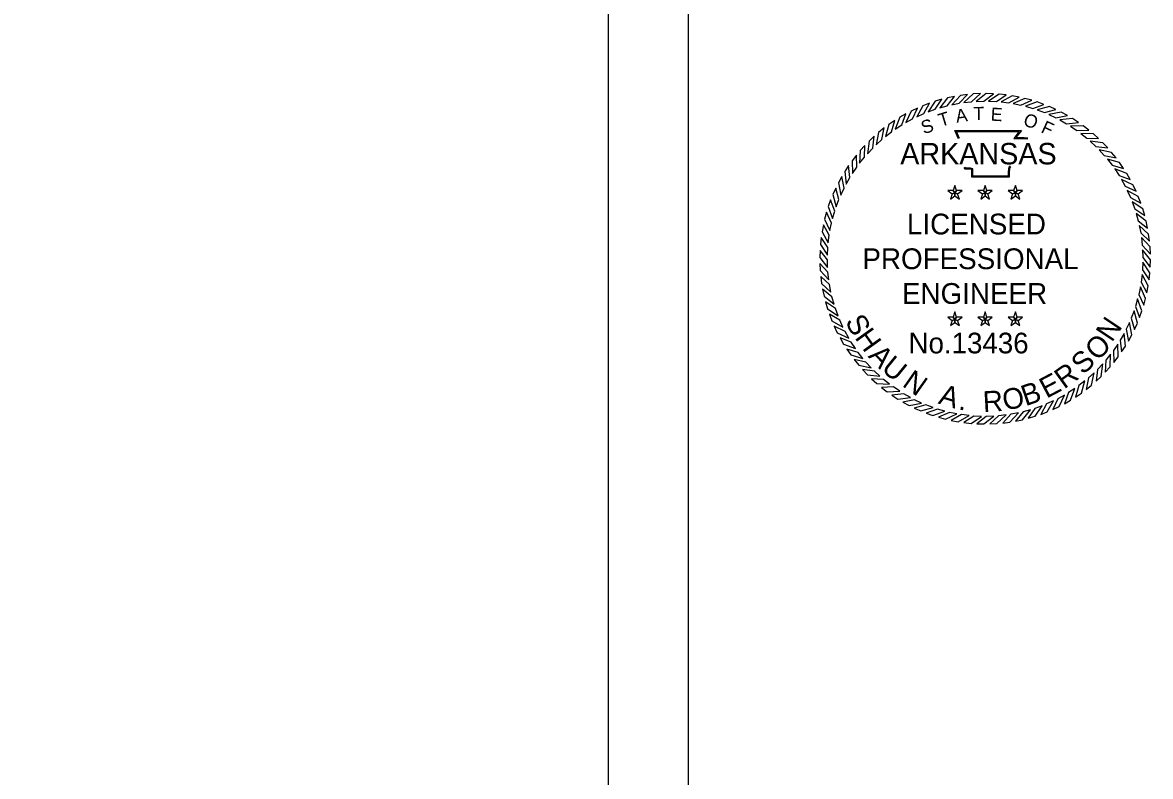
# Model space of a CAD drawing. Extents: x 759422 to 1402138, y 1662254 to 1956530.
# Drawn here: x 1401731 to 1402138, y 1955984.9 to 1956257.2 of the extents above; entities that cross this region are included whole.
import ezdxf

# ---------------------------------------------------------------- set-up
doc = ezdxf.new("R2010")
doc.units = 0
doc.layers.add('1', color=7, linetype='Continuous')
doc.layers.add('G-ANNO-SYMB', color=7, linetype='Continuous')

msp = doc.modelspace()

# ---------------------------------------------------------------- linework, layer by layer
at = {"layer": '1'}
msp.add_line((1401942.43, 1955459.2), (1401942.43, 1956501.52), dxfattribs=at)
msp.add_lwpolyline([(1401971.27, 1956530.36), (1400271.27, 1956530.36), (1400271.27, 1955430.36), (1401971.27, 1955430.36)], close=True, dxfattribs=at)
at = {"layer": 'G-ANNO-SYMB'}
for points in [[(1402058.26, 1956228.04), (1402055.87, 1956227.13), (1402053.61, 1956223.15), (1402056.14, 1956224.29)], [(1402062.73, 1956229.44), (1402060.27, 1956228.72), (1402057.72, 1956224.93), (1402060.32, 1956225.86)], [(1402067.3, 1956230.48), (1402064.79, 1956229.96), (1402061.94, 1956226.38), (1402064.62, 1956227.11)], [(1402071.93, 1956231.17), (1402069.39, 1956230.84), (1402066.27, 1956227.49), (1402068.99, 1956228.01)], [(1402076.61, 1956231.48), (1402074.05, 1956231.36), (1402070.67, 1956228.27), (1402073.43, 1956228.57)], [(1402081.29, 1956231.43), (1402078.73, 1956231.51), (1402075.12, 1956228.69), (1402077.89, 1956228.78)], [(1402085.96, 1956231.02), (1402083.41, 1956231.29), (1402079.59, 1956228.77), (1402082.36, 1956228.64)], [(1402090.58, 1956230.24), (1402088.06, 1956230.71), (1402084.06, 1956228.49), (1402086.81, 1956228.14)], [(1402095.12, 1956229.09), (1402092.64, 1956229.76), (1402088.48, 1956227.87), (1402091.2, 1956227.31)], [(1402099.56, 1956227.6), (1402097.14, 1956228.46), (1402092.85, 1956226.9), (1402095.51, 1956226.12)], [(1402049.72, 1956224.21), (1402047.5, 1956222.93), (1402045.89, 1956218.65), (1402048.21, 1956220.17)], [(1402053.92, 1956226.29), (1402051.6, 1956225.19), (1402049.67, 1956221.05), (1402052.09, 1956222.39)], [(1402103.87, 1956225.76), (1402101.53, 1956226.81), (1402097.12, 1956225.59), (1402099.71, 1956224.61)], [(1402108.02, 1956223.59), (1402105.77, 1956224.82), (1402101.28, 1956223.94), (1402103.79, 1956222.77)], [(1402045.7, 1956221.81), (1402043.58, 1956220.36), (1402042.32, 1956215.96), (1402044.51, 1956217.66)], [(1402111.99, 1956221.1), (1402109.84, 1956222.5), (1402105.29, 1956221.98), (1402107.7, 1956220.61)], [(1402115.75, 1956218.3), (1402113.71, 1956219.87), (1402109.14, 1956219.71), (1402111.44, 1956218.15)], [(1402038.29, 1956216.09), (1402036.42, 1956214.33), (1402035.86, 1956209.79), (1402037.76, 1956211.81)], [(1402041.88, 1956219.09), (1402039.88, 1956217.48), (1402038.97, 1956213), (1402041.02, 1956214.87)], [(1402119.28, 1956215.22), (1402117.37, 1956216.94), (1402112.8, 1956217.14), (1402114.97, 1956215.41)], [(1402034.94, 1956212.81), (1402033.22, 1956210.91), (1402033.02, 1956206.34), (1402034.75, 1956208.51)], [(1402122.55, 1956211.88), (1402120.79, 1956213.74), (1402116.25, 1956214.3), (1402118.27, 1956212.4)], [(1402031.86, 1956209.28), (1402030.29, 1956207.25), (1402030.45, 1956202.68), (1402032.01, 1956204.97)], [(1402125.56, 1956208.28), (1402123.95, 1956210.28), (1402119.47, 1956211.19), (1402121.33, 1956209.14)], [(1402128.27, 1956204.46), (1402126.82, 1956206.58), (1402122.43, 1956207.84), (1402124.13, 1956205.65)], [(1402029.07, 1956205.52), (1402027.66, 1956203.37), (1402028.18, 1956198.83), (1402029.55, 1956201.24)], [(1402130.67, 1956200.44), (1402129.4, 1956202.67), (1402125.11, 1956204.27), (1402126.64, 1956201.95)], [(1402026.58, 1956201.56), (1402025.35, 1956199.3), (1402026.22, 1956194.81), (1402027.4, 1956197.32)], [(1402132.76, 1956196.25), (1402131.66, 1956198.56), (1402127.51, 1956200.5), (1402128.85, 1956198.07)], [(1402024.4, 1956197.4), (1402023.36, 1956195.06), (1402024.58, 1956190.66), (1402025.56, 1956193.25)], [(1402067.4, 1956195.61), (1402066.79, 1956196.45), (1402064.81, 1956196.45), (1402066.41, 1956195.28)], [(1402067.4, 1956195.61), (1402066.41, 1956195.28), (1402065.8, 1956193.4), (1402067.4, 1956194.56)], [(1402067.4, 1956195.61), (1402068.02, 1956196.45), (1402067.4, 1956198.33), (1402066.79, 1956196.45)], [(1402067.4, 1956195.61), (1402068.39, 1956195.28), (1402070, 1956196.45), (1402068.02, 1956196.45)], [(1402067.4, 1956195.61), (1402067.4, 1956194.56), (1402069.01, 1956193.4), (1402068.39, 1956195.28)], [(1402078.31, 1956195.61), (1402077.7, 1956196.45), (1402075.72, 1956196.45), (1402077.32, 1956195.28)], [(1402078.31, 1956195.61), (1402077.32, 1956195.28), (1402076.71, 1956193.4), (1402078.31, 1956194.56)], [(1402078.31, 1956195.61), (1402078.93, 1956196.45), (1402078.31, 1956198.33), (1402077.7, 1956196.45)], [(1402078.31, 1956195.61), (1402079.3, 1956195.28), (1402080.91, 1956196.45), (1402078.93, 1956196.45)], [(1402078.31, 1956195.61), (1402078.31, 1956194.56), (1402079.92, 1956193.4), (1402079.3, 1956195.28)], [(1402089.22, 1956195.61), (1402088.61, 1956196.45), (1402086.63, 1956196.45), (1402088.23, 1956195.28)], [(1402089.22, 1956195.61), (1402088.23, 1956195.28), (1402087.62, 1956193.4), (1402089.22, 1956194.56)], [(1402089.22, 1956195.61), (1402089.83, 1956196.45), (1402089.22, 1956198.33), (1402088.61, 1956196.45)], [(1402089.22, 1956195.61), (1402090.21, 1956195.28), (1402091.82, 1956196.45), (1402089.83, 1956196.45)], [(1402089.22, 1956195.61), (1402089.22, 1956194.56), (1402090.83, 1956193.4), (1402090.21, 1956195.28)], [(1402134.5, 1956191.9), (1402133.59, 1956194.3), (1402129.61, 1956196.55), (1402130.75, 1956194.02)], [(1402022.57, 1956193.1), (1402021.7, 1956190.68), (1402023.27, 1956186.38), (1402024.04, 1956189.04)], [(1402135.9, 1956187.43), (1402135.18, 1956189.89), (1402131.39, 1956192.45), (1402132.33, 1956189.84)], [(1402021.07, 1956188.66), (1402020.4, 1956186.18), (1402022.3, 1956182.02), (1402022.86, 1956184.73)], [(1402136.95, 1956182.86), (1402136.42, 1956185.37), (1402132.84, 1956188.22), (1402133.57, 1956185.55)], [(1402019.93, 1956184.11), (1402019.45, 1956181.59), (1402021.67, 1956177.59), (1402022.02, 1956180.34)], [(1402137.63, 1956178.23), (1402137.3, 1956180.77), (1402133.96, 1956183.89), (1402134.48, 1956181.17)], [(1402019.15, 1956179.49), (1402018.87, 1956176.94), (1402021.4, 1956173.13), (1402021.53, 1956175.9)], [(1402137.95, 1956173.55), (1402137.82, 1956176.12), (1402134.73, 1956179.49), (1402135.04, 1956176.73)], [(1402137.9, 1956168.87), (1402137.97, 1956171.44), (1402135.16, 1956175.04), (1402135.24, 1956172.27)], [(1402018.73, 1956174.83), (1402018.66, 1956172.26), (1402021.47, 1956168.66), (1402021.38, 1956171.43)], [(1402018.68, 1956170.14), (1402018.81, 1956167.58), (1402021.9, 1956164.21), (1402021.59, 1956166.97)], [(1402137.48, 1956164.2), (1402137.75, 1956166.76), (1402135.23, 1956170.57), (1402135.1, 1956167.8)], [(1402019, 1956165.47), (1402019.32, 1956162.93), (1402022.67, 1956159.81), (1402022.15, 1956162.53)], [(1402136.7, 1956159.59), (1402137.17, 1956162.11), (1402134.96, 1956166.11), (1402134.61, 1956163.36)], [(1402019.68, 1956160.84), (1402020.21, 1956158.33), (1402023.79, 1956155.48), (1402023.05, 1956158.15)], [(1402135.56, 1956155.04), (1402136.23, 1956157.52), (1402134.33, 1956161.68), (1402133.77, 1956158.97)], [(1402020.72, 1956156.27), (1402021.45, 1956153.81), (1402025.24, 1956151.25), (1402024.3, 1956153.86)], [(1402134.06, 1956150.6), (1402134.92, 1956153.02), (1402133.36, 1956157.32), (1402132.59, 1956154.66)], [(1402022.12, 1956151.8), (1402023.04, 1956149.4), (1402027.02, 1956147.15), (1402025.88, 1956149.68)], [(1402067.4, 1956149.92), (1402066.79, 1956150.77), (1402064.81, 1956150.77), (1402066.41, 1956149.6)], [(1402067.4, 1956149.92), (1402068.02, 1956150.77), (1402067.4, 1956152.65), (1402066.79, 1956150.77)], [(1402067.4, 1956149.92), (1402068.39, 1956149.6), (1402070, 1956150.77), (1402068.02, 1956150.77)], [(1402078.31, 1956149.92), (1402077.7, 1956150.77), (1402075.72, 1956150.77), (1402077.32, 1956149.6)], [(1402078.31, 1956149.92), (1402078.93, 1956150.77), (1402078.31, 1956152.65), (1402077.7, 1956150.77)], [(1402078.31, 1956149.92), (1402079.3, 1956149.6), (1402080.91, 1956150.77), (1402078.93, 1956150.77)], [(1402089.22, 1956149.92), (1402088.61, 1956150.77), (1402086.63, 1956150.77), (1402088.23, 1956149.6)], [(1402089.22, 1956149.92), (1402089.83, 1956150.77), (1402089.22, 1956152.65), (1402088.61, 1956150.77)], [(1402089.22, 1956149.92), (1402090.21, 1956149.6), (1402091.82, 1956150.77), (1402089.83, 1956150.77)], [(1402132.22, 1956146.3), (1402133.27, 1956148.64), (1402132.05, 1956153.04), (1402131.07, 1956150.45)], [(1402023.87, 1956147.45), (1402024.97, 1956145.14), (1402029.11, 1956143.2), (1402027.78, 1956145.63)], [(1402067.4, 1956149.92), (1402066.41, 1956149.6), (1402065.8, 1956147.72), (1402067.4, 1956148.88)], [(1402067.4, 1956149.92), (1402067.4, 1956148.88), (1402069.01, 1956147.72), (1402068.39, 1956149.6)], [(1402078.31, 1956149.92), (1402077.32, 1956149.6), (1402076.71, 1956147.72), (1402078.31, 1956148.88)], [(1402078.31, 1956149.92), (1402078.31, 1956148.88), (1402079.92, 1956147.72), (1402079.3, 1956149.6)], [(1402089.22, 1956149.92), (1402088.23, 1956149.6), (1402087.62, 1956147.72), (1402089.22, 1956148.88)], [(1402089.22, 1956149.92), (1402089.22, 1956148.88), (1402090.83, 1956147.72), (1402090.21, 1956149.6)], [(1402130.05, 1956142.14), (1402131.28, 1956144.4), (1402130.41, 1956148.88), (1402129.23, 1956146.38)], [(1402025.95, 1956143.26), (1402027.23, 1956141.03), (1402031.51, 1956139.43), (1402029.99, 1956141.75)], [(1402127.56, 1956138.18), (1402128.96, 1956140.33), (1402128.45, 1956144.87), (1402127.07, 1956142.46)], [(1402028.36, 1956139.24), (1402029.81, 1956137.12), (1402034.2, 1956135.86), (1402032.5, 1956138.05)], [(1402124.77, 1956134.42), (1402126.33, 1956136.45), (1402126.17, 1956141.02), (1402124.62, 1956138.73)], [(1402031.07, 1956135.42), (1402032.68, 1956133.42), (1402037.16, 1956132.51), (1402035.29, 1956134.56)], [(1402121.69, 1956130.89), (1402123.41, 1956132.79), (1402123.61, 1956137.36), (1402121.88, 1956135.19)], [(1402034.07, 1956131.82), (1402035.84, 1956129.96), (1402040.37, 1956129.4), (1402038.35, 1956131.3)], [(1402114.75, 1956124.61), (1402116.74, 1956126.22), (1402117.65, 1956130.7), (1402115.6, 1956128.83)], [(1402118.34, 1956127.61), (1402120.2, 1956129.37), (1402120.76, 1956133.91), (1402118.87, 1956131.89)], [(1402037.35, 1956128.48), (1402039.25, 1956126.75), (1402043.82, 1956126.56), (1402041.66, 1956128.29)], [(1402110.93, 1956121.89), (1402113.04, 1956123.34), (1402114.3, 1956127.74), (1402112.11, 1956126.04)], [(1402040.88, 1956125.4), (1402042.91, 1956123.83), (1402047.48, 1956123.99), (1402045.19, 1956125.55)], [(1402044.64, 1956122.6), (1402046.79, 1956121.2), (1402051.33, 1956121.72), (1402048.92, 1956123.09)], [(1402102.71, 1956117.41), (1402105.03, 1956118.51), (1402106.96, 1956122.65), (1402104.53, 1956121.31)], [(1402106.91, 1956119.49), (1402109.13, 1956120.77), (1402110.73, 1956125.05), (1402108.42, 1956123.53)], [(1402048.61, 1956120.11), (1402050.86, 1956118.88), (1402055.35, 1956119.75), (1402052.84, 1956120.93)], [(1402052.76, 1956117.94), (1402055.1, 1956116.89), (1402059.51, 1956118.11), (1402056.91, 1956119.09)], [(1402093.89, 1956114.26), (1402096.35, 1956114.98), (1402098.91, 1956118.77), (1402096.3, 1956117.83)], [(1402098.36, 1956115.66), (1402100.76, 1956116.57), (1402103.01, 1956120.55), (1402100.49, 1956119.41)], [(1402057.07, 1956116.1), (1402059.48, 1956115.24), (1402063.78, 1956116.8), (1402061.12, 1956117.58)], [(1402061.51, 1956114.61), (1402063.98, 1956113.94), (1402068.14, 1956115.83), (1402065.43, 1956116.39)], [(1402066.05, 1956113.46), (1402068.57, 1956112.99), (1402072.57, 1956115.21), (1402069.82, 1956115.55)], [(1402070.67, 1956112.68), (1402073.22, 1956112.41), (1402077.03, 1956114.93), (1402074.26, 1956115.06)], [(1402075.33, 1956112.26), (1402077.9, 1956112.19), (1402081.5, 1956115.01), (1402078.73, 1956114.92)], [(1402080.02, 1956112.21), (1402082.58, 1956112.34), (1402085.95, 1956115.43), (1402083.2, 1956115.13)], [(1402084.69, 1956112.53), (1402087.24, 1956112.86), (1402090.35, 1956116.21), (1402087.63, 1956115.69)], [(1402089.33, 1956113.22), (1402091.84, 1956113.74), (1402094.68, 1956117.32), (1402092.01, 1956116.59)]]:
    msp.add_lwpolyline(points, close=True, dxfattribs=at)
for points in [[(1402068.76, 1956215.15), (1402067.36, 1956218.16), (1402091.43, 1956218.18), (1402089.42, 1956215.65), (1402091.05, 1956215.67), (1402092.42, 1956215.69), (1402093.78, 1956215.54)], [(1402069.1, 1956215.31), (1402067.96, 1956217.78), (1402090.64, 1956217.79), (1402088.62, 1956215.26), (1402091.06, 1956215.29), (1402092.4, 1956215.31), (1402093.74, 1956215.16)], [(1402087.64, 1956205.07), (1402087.23, 1956204.73), (1402087.09, 1956204.23), (1402086.95, 1956202.99), (1402086.95, 1956201.32), (1402073.52, 1956201.32), (1402073.52, 1956203.57), (1402073.52, 1956204.07), (1402072.98, 1956204.23), (1402071.06, 1956204.23), (1402070.73, 1956204.75)], [(1402087.4, 1956205.36), (1402086.89, 1956204.95), (1402086.71, 1956204.3), (1402086.57, 1956203.01), (1402086.57, 1956201.7), (1402073.9, 1956201.7), (1402073.9, 1956203.57), (1402073.9, 1956204.35), (1402073.03, 1956204.61), (1402071.27, 1956204.61), (1402071.04, 1956204.96)]]:
    msp.add_lwpolyline(points, dxfattribs=at)

# ---------------------------------------------------------------- texts
for s, height, rotation, p in [('T', 4.75, 16.9015, (1402062.26, 1956219.44)), ('A', 4.75, 8.6788, (1402068.02, 1956220.94)), ('T', 4.75, 1.4789, (1402074.15, 1956221.89)), ('E', 4.75, 356.672, (1402080.23, 1956221.74)), ('O', 4.75, 341.2218, (1402091.75, 1956220.12)), ('S', 4.75, 19.7726, (1402056.22, 1956216.73)), ('F', 4.75, 335.3628, (1402098.15, 1956217.61)), ('S', 7.5, 298.1636, (1402027.63, 1956149.25)), ('N', 7.5, 56.1007, (1402124.05, 1956141.42)), ('H', 7.5, 305.619, (1402031.05, 1956143.37)), ('O', 7.5, 44.7757, (1402118.84, 1956134.66)), ('A', 7.5, 313.4472, (1402035.82, 1956136.53)), ('S', 7.5, 43.4878, (1402113.69, 1956129.69)), ('U', 7.5, 320.9026, (1402040.49, 1956131.64)), ('N', 7.5, 324.9326, (1402048.05, 1956126.05)), ('E', 7.5, 27.8315, (1402100.46, 1956121.27)), ('R', 7.5, 35.6597, (1402106.8, 1956124.59)), ('B', 7.5, 18.885, (1402092.88, 1956118.56)), ('A', 7.5, 343.0991, (1402061.12, 1956119.62)), ('R', 7.5, 3.2287, (1402077.69, 1956116.48)), ('O', 7.5, 11.4296, (1402085.36, 1956116.97)), ('.', 7.5, 351.3, (1402068.49, 1956117.43))]:
    msp.add_text(s, height=height, rotation=rotation, dxfattribs=at).set_placement(p)
for s, height, p in [('ARKANSAS', 7.747, (1402047.69, 1956205.93)), ('LICENSED', 7.5, (1402050.1, 1956180.64)), ('PROFESSIONAL', 7.5, (1402034.03, 1956168.1)), ('ENGINEER', 7.5, (1402048.31, 1956155.56)), ('No.13436', 7.47, (1402050.68, 1956137.68))]:
    msp.add_text(s, height=height, dxfattribs=at).set_placement(p)

doc.saveas('drawing.dxf')
